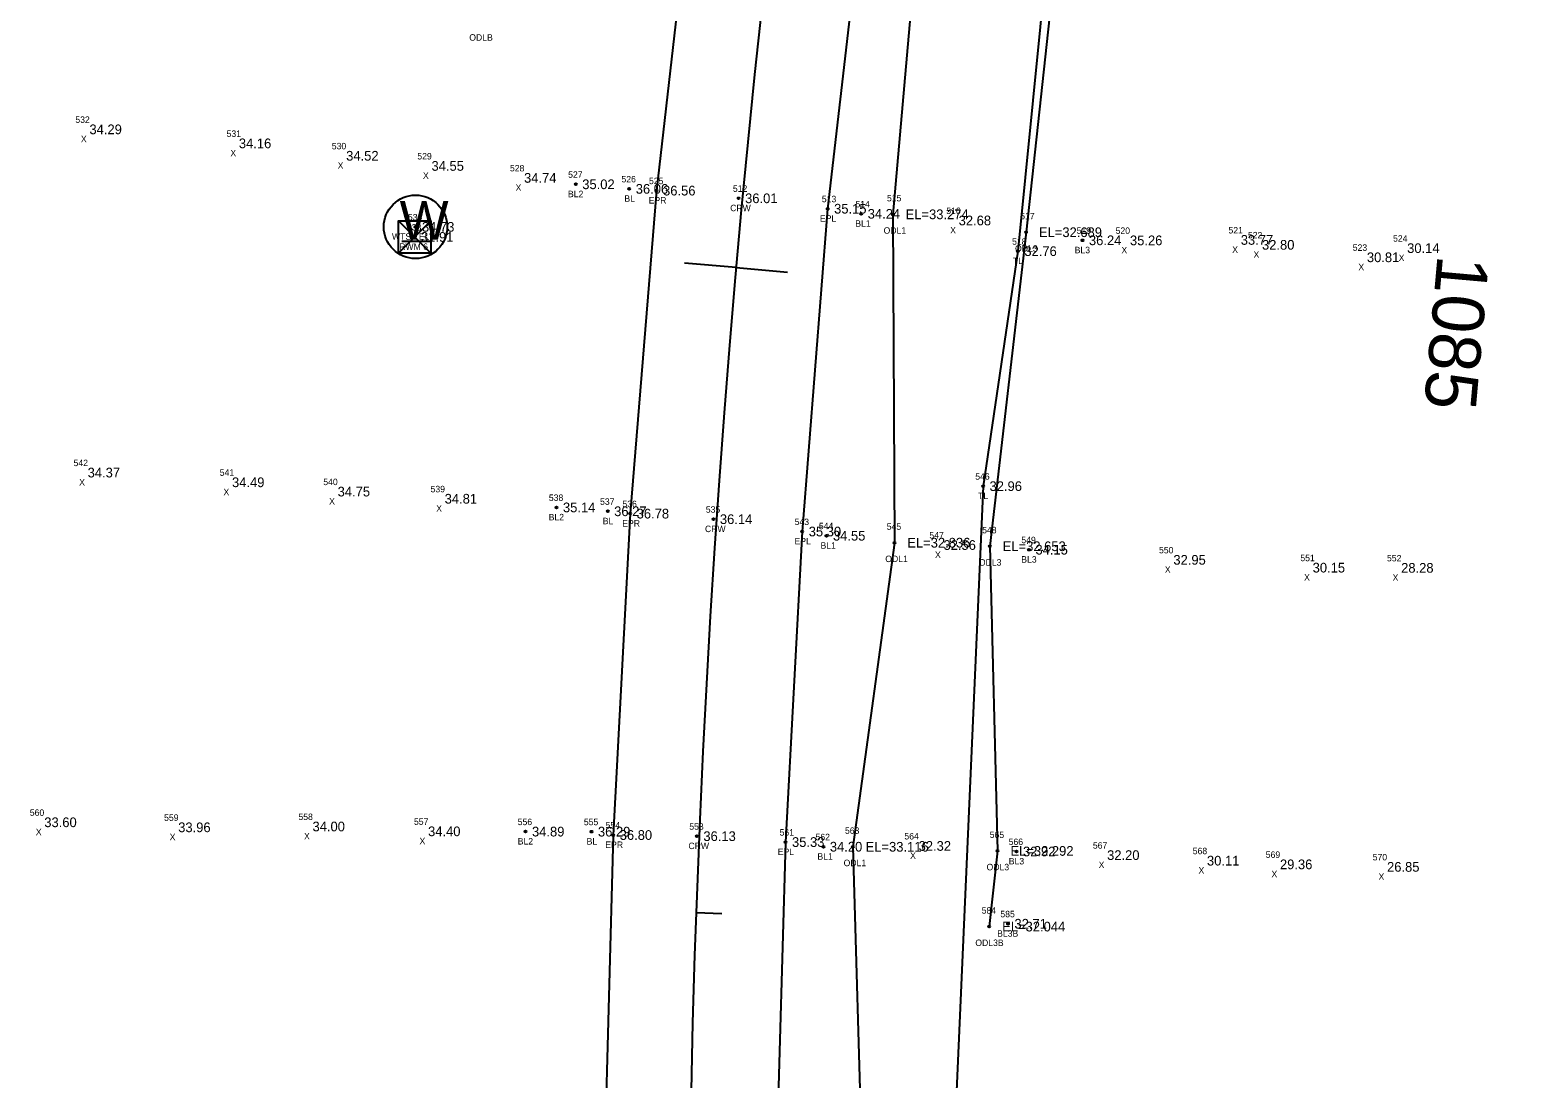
# Model space of a CAD drawing. Extents: x 2042117 to 2045853, y 303080 to 309569.
# Drawn here: x 2042738.1 to 2042971.5, y 307391.1 to 307553.4 of the extents above; entities that cross this region are included whole.
import ezdxf

# ---------------------------------------------------------------- set-up
doc = ezdxf.new("R2010")
doc.units = 0
for name, color, linetype in [('RD_DTM_BkLn_txCode', 7, 'Continuous'), ('RD_EX_H2O', 7, 'Continuous'), ('RD_EX_H2O_txCode', 7, 'Continuous'), ('RD_EX_Misc_txCode', 7, 'Continuous'), ('RD_EX_Road', 7, 'Continuous'), ('RD_EX_Road_txCode', 7, 'Continuous'), ('RD_EX_RW', 7, 'Continuous'), ('RD_EX_RW_TxCode', 7, 'Continuous'), ('RD_EX_TX_H2O_ELEV', 7, 'Continuous'), ('RD_EX_TX_Misc_ELEV', 7, 'Continuous'), ('RD_EX_TX_Road_ELEV', 7, 'Continuous'), ('RD_EX_TX_RW_ELEV', 7, 'Continuous'), ('RD_EX_TX_UT_ELEV', 7, 'Continuous'), ('RD_EX_TX_VEG_ELEV', 7, 'Continuous'), ('RD_EX_UT', 7, 'Continuous'), ('RD_EX_UT_txCode', 7, 'Continuous'), ('RD_EX_VEG', 7, 'Continuous'), ('RD_EX_VEG_txCode', 7, 'Continuous'), ('RD_HC_Cl', 7, 'Continuous'), ('RD_HC_Data_Tic', 7, 'Continuous'), ('RD_HC_Survey_ELEV', 7, 'Continuous'), ('RD_HC_Survey_txCode', 7, 'Continuous'), ('RD_HC_TX_Sta50', 7, 'Continuous'), ('RD_SMD_Locator', 7, 'Continuous')]:
    doc.layers.add(name, color=color, linetype=linetype)

msp = doc.modelspace()

# ---------------------------------------------------------------- linework, layer by layer
at = {"layer": 'RD_EX_H2O'}
for points in [[(2042910.65, 307652.18), (2042905.42, 307621.57), (2042897.72, 307572.16), (2042892.26, 307522.14), (2042886.65, 307473.55), (2042887.85, 307426.41), (2042886.57, 307414.7)], [(2042877.76, 307594.41), (2042875.95, 307574.24), (2042871.62, 307524.91), (2042871.88, 307474.1), (2042865.43, 307427.05), (2042866.84, 307378.87)]]:
    msp.add_lwpolyline(points, dxfattribs=at)
at = {"layer": 'RD_EX_Road'}
for points in [[(2043150.45, 308415.87), (2043123.31, 308373.62), (2043097.1, 308331.18), (2043072.09, 308287.75), (2043048.26, 308243.82), (2043025.59, 308198.98), (2043003.92, 308153.61), (2042983.57, 308107.75), (2042964.45, 308061.45), (2042946.64, 308015.14), (2042930.05, 307967.71), (2042914.65, 307920.21), (2042900.21, 307872.25), (2042887.2, 307823.91), (2042875.38, 307775.02), (2042864.88, 307726.03), (2042855.57, 307677.22), (2042847.6, 307627.85), (2042840.73, 307578.32), (2042835.07, 307528.58), (2042830.98, 307478.6), (2042828.36, 307428.87), (2042826.99, 307378.91)], [(2043172.79, 308402.16), (2043145.1, 308359.37), (2043119.63, 308317.71), (2043094.79, 308274.94), (2043071.92, 308232.51), (2043049.11, 308188.03), (2043027.82, 308142.81), (2043007.75, 308097.66), (2042989.09, 308052.53), (2042971.66, 308006.7), (2042955.42, 307960.12), (2042939.67, 307912.41), (2042925.65, 307865.09), (2042912.69, 307817.39), (2042901.29, 307769.38), (2042891.09, 307720.95), (2042881.8, 307672.88), (2042874.23, 307624.44), (2042867.25, 307575.38), (2042861.55, 307525.78), (2042857.62, 307475.83), (2042855.03, 307427.78), (2042853.64, 307379.19)]]:
    msp.add_lwpolyline(points, dxfattribs=at)
at = {"layer": 'RD_EX_RW'}
for p, q in [((2042795.1, 307518.91), (2042800.1, 307523.91)), ((2042800.1, 307518.91), (2042795.1, 307523.91)), ((2042800.1, 307523.91), (2042800.1, 307518.91))]:
    msp.add_line(p, q, dxfattribs=at)
msp.add_lwpolyline([(2042795.1, 307518.91), (2042795.1, 307523.91), (2042800.1, 307523.91), (2042800.1, 307518.91)], close=True, dxfattribs=at)
at = {"layer": 'RD_EX_UT'}
msp.add_line((2042795.62, 307520.76), (2042800.25, 307520.76), dxfattribs=at)
msp.add_circle((2042797.75, 307522.97), 4.91, dxfattribs=at)
at = {"layer": 'RD_EX_VEG'}
msp.add_lwpolyline([(2043048.7, 308112.2), (2043032.62, 308087.68), (2043027.55, 308080.82), (2043013.5, 308043.09), (2042994.71, 307997.39), (2042983.47, 307967.75), (2042952.97, 307870.73), (2042935.66, 307809.47), (2042918.92, 307737.74), (2042902.79, 307636.4), (2042902.54, 307635.29), (2042891, 307519.21), (2042885.61, 307482.85), (2042881.1, 307379.92)], dxfattribs=at)
at = {"layer": 'RD_HC_Cl'}
msp.add_arc((2044751.25, 307348.43), 1911.29, 137.68184, 219.86836, dxfattribs=at)
at = {"layer": 'RD_HC_Data_Tic'}
for p, q in [((2042847.38, 307516.68), (2042839.41, 307517.38)), ((2042847.38, 307516.68), (2042855.34, 307515.97)), ((2042841.18, 307416.88), (2042845.18, 307416.74))]:
    msp.add_line(p, q, dxfattribs=at)
at = {"layer": 'RD_SMD_Locator'}
for centre in [(2042822.56, 307529.56), (2042830.84, 307528.85), (2042835.07, 307528.58), (2042847.77, 307527.39), (2042861.55, 307525.78), (2042866.75, 307524.99), (2042871.62, 307524.91), (2042797.75, 307522.97), (2042797.6, 307521.41), (2042892.26, 307522.14), (2042901, 307520.89), (2042891, 307519.21), (2042885.61, 307482.85), (2042819.57, 307479.56), (2042827.5, 307478.96), (2042830.98, 307478.6), (2042843.87, 307477.74), (2042857.62, 307475.83), (2042861.37, 307475.18), (2042871.88, 307474.1), (2042886.65, 307473.55), (2042892.72, 307473.02), (2042814.78, 307429.4), (2042824.99, 307429.39), (2042828.36, 307428.87), (2042841.31, 307428.69), (2042855.03, 307427.78), (2042860.89, 307427.06), (2042865.43, 307427.05), (2042887.85, 307426.41), (2042890.79, 307426.32), (2042889.47, 307415.14), (2042886.57, 307414.7)]:
    msp.add_circle(centre, 0.15, dxfattribs=at)

# ---------------------------------------------------------------- texts
at = {"layer": 'RD_DTM_BkLn_txCode'}
for s, p in [('527', (2042821.38, 307530.56)), ('526', (2042829.63, 307529.85)), ('BL2', (2042821.35, 307527.56)), ('BL', (2042830.08, 307526.85)), ('514', (2042865.86, 307525.99)), ('BL1', (2042865.83, 307522.99)), ('519', (2042900.1, 307521.89)), ('BL3', (2042899.79, 307518.89)), ('538', (2042818.39, 307480.56)), ('537', (2042826.32, 307479.96)), ('BL2', (2042818.36, 307477.56)), ('BL', (2042826.74, 307476.96)), ('544', (2042860.19, 307476.18)), ('BL1', (2042860.45, 307473.18)), ('549', (2042891.54, 307474.02)), ('BL3', (2042891.52, 307471.02)), ('556', (2042813.57, 307430.4)), ('555', (2042823.81, 307430.39)), ('BL2', (2042813.57, 307427.4)), ('BL', (2042824.24, 307427.39)), ('562', (2042859.68, 307428.06)), ('566', (2042889.57, 307427.32)), ('BL1', (2042859.97, 307425.06)), ('BL3', (2042889.59, 307424.32)), ('585', (2042888.29, 307416.14)), ('BL3B', (2042887.79, 307413.14))]:
    msp.add_text(s, height=1, dxfattribs=at).set_placement(p)
at = {"layer": 'RD_EX_H2O_txCode'}
for s, p in [('ODLB', (2042806.07, 307551.78)), ('515', (2042870.73, 307526.91)), ('517', (2042891.36, 307524.14)), ('ODL1', (2042870.21, 307521.91)), ('ODL3', (2042890.56, 307519.14)), ('545', (2042870.7, 307476.1)), ('548', (2042885.47, 307475.55)), ('ODL1', (2042870.47, 307471.1)), ('ODL3', (2042884.96, 307470.55)), ('563', (2042864.23, 307429.05)), ('565', (2042886.64, 307428.41)), ('ODL1', (2042864.02, 307424.05)), ('ODL3', (2042886.15, 307423.41)), ('584', (2042885.39, 307416.7)), ('ODL3B', (2042884.41, 307411.7))]:
    msp.add_text(s, height=1, dxfattribs=at).set_placement(p)
at = {"layer": 'RD_EX_Misc_txCode'}
for s, p in [('532', (2042745.09, 307539.06)), ('X', (2042745.95, 307536.06)), ('531', (2042768.5, 307536.89)), ('X', (2042769.09, 307533.89)), ('530', (2042784.79, 307534.97)), ('529', (2042798.03, 307533.4)), ('X', (2042785.7, 307531.97)), ('528', (2042812.37, 307531.55)), ('X', (2042798.9, 307530.4)), ('X', (2042813.24, 307528.55)), ('516', (2042879.91, 307524.96)), ('X', (2042880.52, 307521.96)), ('520', (2042906.13, 307521.88)), ('521', (2042923.6, 307521.95)), ('522', (2042926.61, 307521.19)), ('523', (2042942.84, 307519.26)), ('524', (2042949.08, 307520.68)), ('X', (2042907.03, 307518.88)), ('X', (2042924.18, 307518.95)), ('X', (2042927.48, 307518.19)), ('X', (2042949.95, 307517.68)), ('X', (2042943.71, 307516.26)), ('542', (2042744.81, 307485.95)), ('541', (2042767.44, 307484.45)), ('X', (2042745.68, 307482.95)), ('540', (2042783.47, 307483.01)), ('539', (2042800.08, 307481.9)), ('X', (2042768.02, 307481.45)), ('X', (2042784.38, 307480.01)), ('X', (2042800.95, 307478.9)), ('547', (2042877.3, 307474.74)), ('X', (2042878.17, 307471.74)), ('550', (2042912.85, 307472.45)), ('551', (2042934.73, 307471.24)), ('552', (2042948.14, 307471.21)), ('X', (2042913.75, 307469.45)), ('X', (2042935.31, 307468.24)), ('X', (2042949.01, 307468.21)), ('560', (2042738.04, 307431.84)), ('559', (2042758.83, 307431.06)), ('558', (2042779.62, 307431.19)), ('X', (2042738.97, 307428.84)), ('X', (2042780.49, 307428.19)), ('557', (2042797.51, 307430.44)), ('564', (2042873.43, 307428.18)), ('X', (2042759.69, 307428.06)), ('X', (2042798.37, 307427.44)), ('567', (2042902.61, 307426.76)), ('568', (2042918.07, 307425.9)), ('X', (2042874.32, 307425.18)), ('X', (2042903.5, 307423.76)), ('569', (2042929.37, 307425.33)), ('570', (2042945.93, 307424.94)), ('X', (2042918.96, 307422.9)), ('X', (2042930.26, 307422.33)), ('X', (2042946.83, 307421.94))]:
    msp.add_text(s, height=1, dxfattribs=at).set_placement(p)
at = {"layer": 'RD_EX_Road_txCode'}
for s, p in [('525', (2042833.89, 307529.58)), ('EPR', (2042833.84, 307526.58)), ('513', (2042860.65, 307526.78)), ('EPL', (2042860.35, 307523.78)), ('536', (2042829.78, 307479.6)), ('EPR', (2042829.75, 307476.6)), ('543', (2042856.44, 307476.83)), ('EPL', (2042856.42, 307473.83)), ('554', (2042827.18, 307429.87)), ('561', (2042854.11, 307428.78)), ('EPR', (2042827.13, 307426.87)), ('EPL', (2042853.83, 307425.78))]:
    msp.add_text(s, height=1, dxfattribs=at).set_placement(p)
at = {"layer": 'RD_EX_RW_TxCode'}
for s, p in [('533', (2042796.42, 307522.41)), ('RWM 6', (2042795.22, 307519.41))]:
    msp.add_text(s, height=1, dxfattribs=at).set_placement(p)
at = {"layer": 'RD_EX_TX_H2O_ELEV'}
for s, p in [('EL=33.274', (2042873.62, 307524.16)), ('EL=32.689', (2042894.26, 307521.39)), ('EL=32.836', (2042873.88, 307473.35)), ('EL=32.653', (2042888.65, 307472.8)), ('EL=33.116', (2042867.43, 307426.3)), ('EL=32.292', (2042889.85, 307425.66)), ('EL=32.044', (2042888.57, 307413.95))]:
    msp.add_text(s, height=1.5, dxfattribs=at).set_placement(p)
at = {"layer": 'RD_EX_TX_Misc_ELEV'}
for s, p in [('34.29', (2042747.27, 307537.31)), ('34.16', (2042770.4, 307535.14)), ('34.52', (2042787.01, 307533.22)), ('34.55', (2042800.22, 307531.65)), ('34.74', (2042814.55, 307529.8)), ('35.02', (2042823.56, 307528.81)), ('36.06', (2042831.84, 307528.1)), ('34.24', (2042867.75, 307524.24)), ('32.68', (2042881.83, 307523.21)), ('36.24', (2042902, 307520.14)), ('35.26', (2042908.35, 307520.13)), ('33.77', (2042925.5, 307520.2)), ('32.80', (2042928.79, 307519.44)), ('30.14', (2042951.26, 307518.93)), ('30.81', (2042945.03, 307517.51)), ('34.37', (2042746.99, 307484.2)), ('34.49', (2042769.34, 307482.7)), ('34.75', (2042785.69, 307481.26)), ('34.81', (2042802.26, 307480.15)), ('35.14', (2042820.57, 307478.81)), ('36.27', (2042828.5, 307478.21)), ('34.55', (2042862.37, 307474.43)), ('32.56', (2042879.48, 307472.99)), ('34.15', (2042893.72, 307472.27)), ('32.95', (2042915.07, 307470.7)), ('30.15', (2042936.63, 307469.49)), ('28.28', (2042950.33, 307469.46)), ('33.60', (2042740.28, 307430.09)), ('33.96', (2042761.01, 307429.31)), ('34.00', (2042781.8, 307429.44)), ('34.40', (2042799.69, 307428.69)), ('34.89', (2042815.78, 307428.65)), ('36.29', (2042825.99, 307428.64)), ('34.20', (2042861.89, 307426.31)), ('32.32', (2042875.63, 307426.43)), ('32.92', (2042891.79, 307425.57)), ('32.20', (2042904.81, 307425.01)), ('30.11', (2042920.27, 307424.15)), ('29.36', (2042931.57, 307423.58)), ('26.85', (2042948.15, 307423.19)), ('32.71', (2042890.47, 307414.39))]:
    msp.add_text(s, height=1.5, dxfattribs=at).set_placement(p)
at = {"layer": 'RD_EX_TX_Road_ELEV'}
for s, p in [('36.56', (2042836.07, 307527.83)), ('35.15', (2042862.55, 307525.03)), ('36.78', (2042831.98, 307477.85)), ('35.30', (2042858.62, 307475.08)), ('36.80', (2042829.36, 307428.12)), ('35.33', (2042856.03, 307427.03))]:
    msp.add_text(s, height=1.5, dxfattribs=at).set_placement(p)
at = {"layer": 'RD_EX_TX_RW_ELEV'}
msp.add_text('31.91', height=1.5, dxfattribs=at).set_placement((2042798.6, 307520.66))
at = {"layer": 'RD_EX_TX_UT_ELEV'}
msp.add_text('34.73', height=1.5, dxfattribs=at).set_placement((2042798.75, 307522.22))
at = {"layer": 'RD_EX_TX_VEG_ELEV'}
for s, p in [('32.76', (2042892, 307518.46)), ('32.96', (2042886.61, 307482.1))]:
    msp.add_text(s, height=1.5, dxfattribs=at).set_placement(p)
at = {"layer": 'RD_EX_UT'}
msp.add_text('W', height=6, dxfattribs=at).set_placement((2042795.29, 307520.97))
at = {"layer": 'RD_EX_UT_txCode'}
for s, p in [('534', (2042796.57, 307523.97)), ('WTS TELE', (2042794.1, 307520.97))]:
    msp.add_text(s, height=1, dxfattribs=at).set_placement(p)
at = {"layer": 'RD_EX_VEG_txCode'}
for s, p in [('518', (2042890.1, 307520.21)), ('TL', (2042890.23, 307517.21)), ('546', (2042884.4, 307483.85)), ('TL', (2042884.84, 307480.85))]:
    msp.add_text(s, height=1, dxfattribs=at).set_placement(p)
at = {"layer": 'RD_HC_Survey_ELEV'}
for s, p in [('36.01', (2042848.77, 307526.64)), ('36.14', (2042844.87, 307476.99)), ('36.13', (2042842.31, 307427.94))]:
    msp.add_text(s, height=1.5, dxfattribs=at).set_placement(p)
at = {"layer": 'RD_HC_Survey_txCode'}
for s, p in [('512', (2042846.88, 307528.39)), ('CRW', (2042846.46, 307525.39)), ('535', (2042842.69, 307478.74)), ('CRW', (2042842.56, 307475.74)), ('553', (2042840.13, 307429.69)), ('CRW', (2042840, 307426.69))]:
    msp.add_text(s, height=1, dxfattribs=at).set_placement(p)
at = {"layer": 'RD_HC_TX_Sta50'}
msp.add_text('1085', height=8, rotation=264.9499, dxfattribs=at).set_placement((2042955.98, 307518.76))

doc.saveas('drawing.dxf')
